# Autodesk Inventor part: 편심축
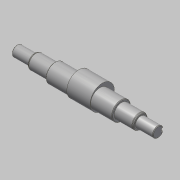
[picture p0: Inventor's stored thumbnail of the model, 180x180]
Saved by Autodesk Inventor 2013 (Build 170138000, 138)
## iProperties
Created: 2015-10
Part Number: 편심축
Document SubType Name: Modeling
Designer: mdu
Density: 7.86 g/cm^3
Material: 강철, 연강
Mass: 1267.06 g
Surface Area: 239.297 cm^2
Volume: 161.203 cm^3
Author: mdu
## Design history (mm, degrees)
sketch "스케치1"
  geometry: L1 (-20.5, -41.331)-(-20.5, 32.669) reference; L2 (7.5, -30.031)-(7.5, 21.369) reference; L3 (135.5, -30.331)-(135.5, 21.669) reference; L4 (121.5, 21.369)-(121.5, -30.031) reference; L5 (184.5, -4.331)-(-57.5, -4.331); L6 (184.5, -4.331)-(184.5, 4.669); L7 (154.5, 8.169)-(121.5, 8.169); L8 (121.5, 8.169)-(121.5, 11.669); L9 (121.5, 11.669)-(7.5, 11.669); L10 (7.5, 11.669)-(7.5, 8.169); L11 (7.5, 8.169)-(-27.5, 8.169); L12 (-27.5, 8.169)-(-27.5, 4.669); L13 (-27.5, 4.669)-(-57.5, 4.669); L14 (-57.5, 4.669)-(-57.5, -4.331); L15 (154.5, 8.169)-(154.5, 4.669); L16 (154.5, 4.669)-(184.5, 4.669); C1 r 32.5 at (64.5, -4.331) reference; 1 further point
  constraints: 24 end point, 8 perpendicular, 5 point on line, 3 parallel, 2 collinear
  dimensions: "d1" = 25 diameter of L11 L5; "d2" = 32 diameter of L9 L5; "d3" = 18 diameter of L13 L5; "d4" = 35 distance of L10.end L11.end; "d5" = 30 distance of L12.end L13.end; "d15" = 33 distance of L7.start L7.end; "d26" = 30 distance of L15.end L6.end
revolve "회전1" sketch "스케치1" stored, may be unused: angle "d6" = 90 deg
node "작업 평면1"
sketch "스케치2"
  geometry: C1 r 16 at (0, 0) reference; C2 r 20.75 at (0, 4)
  constraints: 1 centre point, 1 vertical alignment
  dimensions: "d34" = 4 distance of C2.centre C1.centre; "d35" = 41.5 diameter of C2
extrude "돌출1" join sketch "스케치2" stored distance "d9" = 40; taper "d10" = 0 deg
chamfer "모따기1" distance "d11" = 1; stored, may be unused: second distance "d12" = 2, angle "d13" = 45 deg
node "작업 평면2"
sketch "스케치3"
  geometry: L1 (-15, -8)-(-15, 8) reference; L2 (-15, 3)-(0, 3); L3 (0, -3)-(-15, -3); A1 r 3 centre (0, 0) between (0, -3) and (0, 3); 2 further points
  constraints: 4 end point, 2 perpendicular, 2 point on circle, 2 point on line, 2 tangent, 1 centre point, 1 horizontal alignment, 1 midpoint
  dimensions: "d16" = 18 dimension on A1 L1; "d17" = 6 distance between parallel lines of L3 L2
extrude "돌출2" cut sketch "스케치3" distance "d18" = 3.5; taper "d19" = 0 deg
node "작업 평면3"
chamfer "모따기2" distance "d36" = 2.2; stored, may be unused: second distance "d37" = 2, angle "d38" = 30 deg
chamfer "모따기3" distance "d39" = 2.2; stored, may be unused: second distance "d40" = 2, angle "d41" = 30 deg
fillet "모깎기1" dims "d42" = 1, "d43" = 2
fillet "모깎기2" dims "d44" = 1, "d45" = 2
node "솔리드1"
mirror "대칭1"
node "참조1"
node "참조2"
node "참조3"
node "참조4"
node "참조5"
other parameters: "d30" = 35
